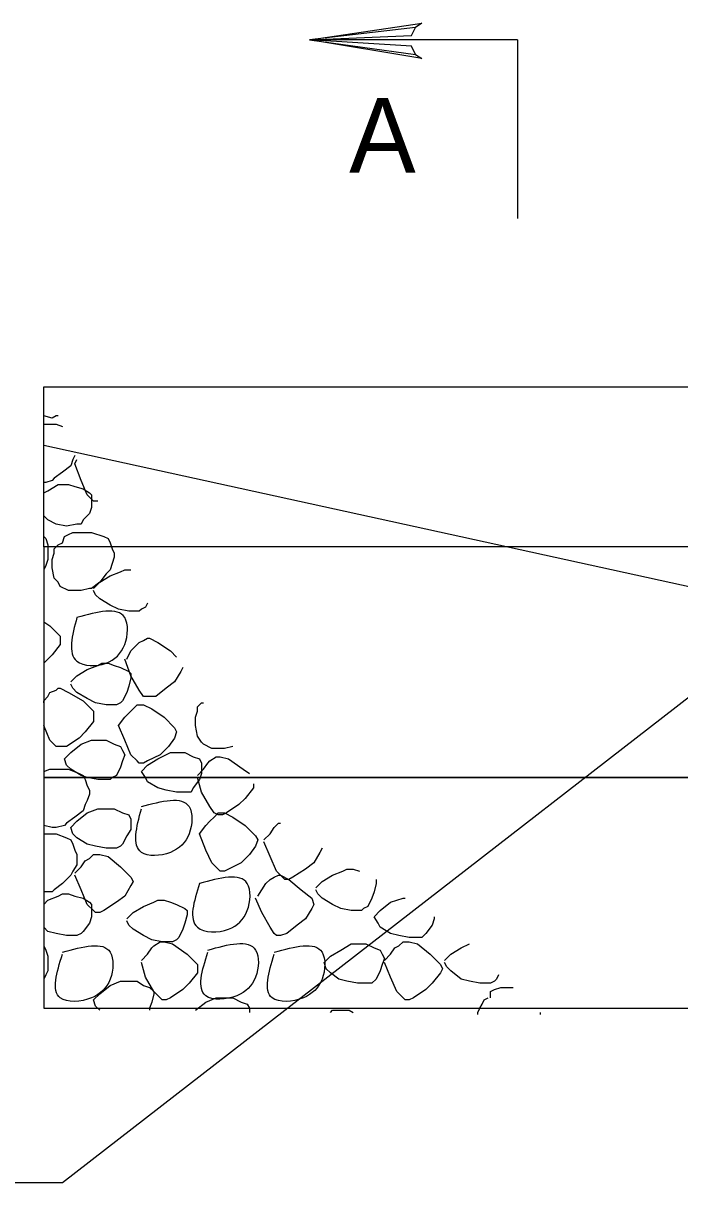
# Model space of a CAD drawing. Extents: x 593 to 1473, y 721 to 1315.
# Drawn here: x 708.2 to 747.7, y 825.5 to 895.3 of the extents above; entities that cross this region are included whole.
import ezdxf

# ---------------------------------------------------------------- set-up
doc = ezdxf.new("R2010")
doc.units = 0
doc.layers.add('2', color=7, linetype='Continuous')

msp = doc.modelspace()

# ---------------------------------------------------------------- linework, layer by layer
at = {"layer": '2'}
for p, q in [((737.959, 894.266), (725.459, 894.266)), ((737.959, 894.266), (737.959, 883.516)), ((709.459, 869.891), (769.334, 856.766)), ((754.959, 859.891), (710.584, 825.516)), ((710.584, 825.516), (663.834, 825.516))]:
    msp.add_line(p, q, dxfattribs=at)
for points in [[(731.834, 893.391), (731.584, 893.891), (725.459, 894.266), (731.834, 893.391), (732.209, 893.141), (725.459, 894.266), (731.584, 894.516), (731.834, 895.016), (725.459, 894.266), (732.209, 895.266), (731.834, 895.016)], [(709.459, 863.766), (709.459, 873.391), (765.709, 873.391)], [(709.959, 871.516), (709.459, 871.641)], [(709.459, 871.641), (709.459, 871.641)], [(710.209, 871.641), (709.959, 871.516)], [(710.334, 871.641), (710.209, 871.641)], [(709.459, 871.141), (709.709, 871.141)], [(709.709, 871.141), (710.209, 871.141)], [(710.209, 871.141), (710.584, 871.016)], [(711.334, 869.266), (711.209, 869.016)], [(711.084, 868.641), (710.584, 868.266)], [(711.209, 869.016), (711.084, 868.641)], [(711.334, 868.766), (711.459, 869.016)], [(711.709, 867.766), (711.334, 868.766)], [(709.959, 867.766), (709.584, 867.641)], [(710.084, 867.891), (709.959, 867.766)], [(710.584, 868.266), (710.084, 867.891)], [(712.084, 866.891), (711.709, 867.766)], [(709.584, 867.641), (709.459, 867.641)], [(709.459, 867.016), (709.709, 867.141)], [(709.709, 867.141), (710.334, 867.516)], [(710.334, 867.516), (710.584, 867.516)], [(710.584, 867.516), (710.959, 867.516)], [(710.959, 867.516), (711.334, 867.391)], [(711.334, 867.391), (711.834, 867.266)], [(711.834, 867.266), (712.209, 867.016)], [(712.209, 867.016), (712.334, 866.891)], [(712.459, 866.516), (712.084, 866.891)], [(712.334, 866.891), (712.334, 866.641)], [(712.334, 866.641), (712.334, 866.141)], [(712.584, 866.516), (712.459, 866.516)], [(712.709, 866.516), (712.584, 866.516)], [(709.709, 865.391), (709.459, 865.641)], [(712.209, 865.766), (711.834, 865.391)], [(712.334, 866.141), (712.209, 865.766)], [(710.209, 865.141), (709.709, 865.391)], [(710.834, 865.016), (710.209, 865.141)], [(711.459, 865.141), (710.834, 865.016)], [(711.709, 865.141), (711.459, 865.141)], [(711.834, 865.391), (711.709, 865.141)], [(709.459, 864.391), (709.584, 864.266)], [(709.584, 864.266), (709.709, 863.891)], [(710.584, 864.016), (710.709, 864.391)], [(710.709, 864.391), (710.959, 864.516)], [(710.959, 864.516), (711.209, 864.641)], [(711.209, 864.641), (711.834, 864.641)], [(711.834, 864.641), (712.334, 864.641)], [(712.334, 864.641), (713.084, 864.391)], [(713.084, 864.391), (713.334, 864.266)], [(713.334, 864.266), (713.459, 864.016)], [(769.459, 863.766), (709.459, 863.766), (709.459, 849.891), (786.959, 849.891), (786.959, 857.141)], [(770.334, 863.766), (709.459, 863.766)], [(709.709, 863.891), (709.709, 863.516)], [(709.709, 863.516), (709.709, 863.266)], [(710.084, 863.641), (710.334, 863.891)], [(710.084, 863.391), (710.084, 863.641)], [(710.334, 863.891), (710.584, 864.016)], [(713.459, 864.016), (713.584, 863.641)], [(713.584, 863.641), (713.709, 863.391)], [(709.709, 863.016), (709.584, 862.641)], [(709.709, 863.266), (709.709, 863.016)], [(709.959, 863.016), (710.084, 863.391)], [(709.959, 862.516), (709.959, 863.016)], [(713.709, 863.141), (713.584, 862.766)], [(713.709, 863.391), (713.709, 863.141)], [(709.584, 862.641), (709.459, 862.391)], [(710.084, 861.891), (709.959, 862.516)], [(713.209, 862.141), (712.834, 861.641)], [(713.459, 862.391), (713.209, 862.141)], [(713.584, 862.766), (713.459, 862.391)], [(713.459, 862.016), (714.084, 862.266)], [(714.084, 862.266), (714.334, 862.391)], [(714.334, 862.391), (714.709, 862.391)], [(714.709, 862.391), (714.709, 862.391)], [(710.334, 861.641), (710.084, 861.891)], [(710.459, 861.391), (710.334, 861.641)], [(712.834, 861.641), (712.334, 861.266)], [(712.459, 861.266), (712.834, 861.641)], [(712.834, 861.641), (713.459, 862.016)], [(710.959, 861.141), (710.459, 861.391)], [(711.459, 861.141), (710.959, 861.141)], [(711.709, 861.141), (711.459, 861.141)], [(712.209, 861.266), (711.709, 861.141)], [(712.334, 861.266), (712.209, 861.266)], [(712.584, 860.891), (712.459, 861.141)], [(712.834, 860.641), (712.584, 860.891)], [(713.459, 860.266), (712.834, 860.641)], [(713.959, 860.016), (713.459, 860.266)], [(715.584, 860.141), (715.334, 860.016)], [(715.709, 860.391), (715.584, 860.141)], [(714.584, 859.891), (713.959, 860.016)], [(715.209, 859.891), (714.584, 859.891)], [(715.334, 860.016), (715.209, 859.891)], [(709.459, 859.266), (709.834, 859.016)], [(709.834, 859.016), (710.459, 858.391)], [(710.459, 858.391), (710.459, 858.141)], [(710.459, 858.141), (710.459, 857.891)], [(714.959, 857.766), (715.209, 858.016)], [(715.209, 858.016), (715.459, 858.141)], [(715.459, 858.141), (715.709, 858.266)], [(715.709, 858.266), (715.834, 858.266)], [(715.834, 858.266), (716.334, 858.016)], [(716.334, 858.016), (717.084, 857.516)], [(709.959, 857.266), (709.584, 856.891)], [(710.459, 857.891), (709.959, 857.266)], [(714.459, 857.016), (714.709, 857.516)], [(714.709, 857.516), (714.959, 857.766)], [(717.084, 857.516), (717.459, 857.141)], [(709.584, 856.891), (709.459, 856.766)], [(712.084, 856.391), (712.709, 856.641)], [(712.709, 856.641), (712.959, 856.766)], [(712.959, 856.766), (713.334, 856.766)], [(713.334, 856.766), (713.709, 856.641)], [(713.709, 856.641), (714.084, 856.516)], [(714.709, 856.016), (714.334, 857.016)], [(711.084, 855.641), (711.459, 856.016)], [(711.459, 856.016), (712.084, 856.391)], [(714.084, 856.516), (714.584, 856.266)], [(714.584, 856.266), (714.709, 856.141)], [(714.709, 855.891), (714.584, 855.391)], [(714.709, 856.141), (714.709, 855.891)], [(715.209, 855.141), (714.709, 856.016)], [(717.709, 856.266), (717.334, 855.641)], [(717.834, 856.516), (717.709, 856.266)], [(709.834, 855.016), (710.209, 855.141)], [(710.209, 855.141), (710.334, 855.266)], [(710.334, 855.266), (710.459, 855.266)], [(710.459, 855.266), (710.959, 855.016)], [(711.209, 855.266), (711.084, 855.516)], [(711.459, 855.016), (711.209, 855.266)], [(714.584, 855.391), (714.459, 855.016)], [(715.459, 854.766), (715.209, 855.141)], [(716.834, 855.266), (716.209, 854.766)], [(717.334, 855.641), (716.834, 855.266)], [(709.459, 854.516), (709.709, 854.766)], [(709.459, 854.391), (709.459, 854.516)], [(709.709, 854.766), (709.834, 855.016)], [(710.959, 855.016), (711.834, 854.516)], [(712.084, 854.641), (711.459, 855.016)], [(711.834, 854.516), (712.459, 853.891)], [(712.584, 854.391), (712.084, 854.641)], [(714.209, 854.516), (714.084, 854.391)], [(714.459, 855.016), (714.209, 854.516)], [(715.709, 854.766), (715.459, 854.766)], [(715.834, 854.766), (715.709, 854.766)], [(716.209, 854.766), (715.834, 854.766)], [(712.459, 853.891), (712.459, 853.516)], [(713.209, 854.266), (712.584, 854.391)], [(713.834, 854.266), (713.209, 854.266)], [(714.084, 854.391), (713.834, 854.266)], [(714.334, 853.516), (714.584, 853.766)], [(714.584, 853.766), (714.834, 854.016)], [(714.834, 854.016), (715.084, 854.266)], [(715.084, 854.266), (715.209, 854.266)], [(715.209, 854.266), (715.459, 854.266)], [(715.459, 854.266), (715.959, 854.016)], [(715.959, 854.016), (716.709, 853.516)], [(718.584, 853.516), (718.709, 853.891)], [(718.709, 854.141), (718.959, 854.391)], [(718.709, 853.891), (718.709, 854.141)], [(718.959, 854.391), (719.084, 854.391)], [(712.459, 853.266), (711.959, 852.641)], [(712.459, 853.516), (712.459, 853.266)], [(713.959, 853.016), (714.334, 853.516)], [(716.709, 853.516), (717.334, 852.891)], [(718.584, 853.016), (718.584, 853.516)], [(709.834, 852.141), (709.459, 853.016)], [(711.959, 852.641), (711.584, 852.266)], [(714.334, 852.141), (713.959, 853.016)], [(717.334, 852.891), (717.459, 852.641)], [(717.459, 852.641), (717.334, 852.266)], [(718.709, 852.391), (718.584, 853.016)], [(718.959, 852.016), (718.709, 852.391)], [(710.209, 851.766), (709.834, 852.141)], [(710.334, 851.766), (710.209, 851.766)], [(710.584, 851.766), (710.334, 851.766)], [(710.834, 851.766), (710.584, 851.766)], [(711.584, 852.266), (710.834, 851.766)], [(711.084, 851.391), (711.709, 851.891)], [(711.709, 851.891), (712.334, 852.141)], [(712.334, 852.141), (712.584, 852.141)], [(712.584, 852.141), (712.959, 852.141)], [(712.959, 852.141), (713.209, 852.141)], [(713.209, 852.141), (713.709, 851.891)], [(713.709, 851.891), (714.084, 851.766)], [(714.084, 851.766), (714.209, 851.516)], [(714.709, 851.266), (714.334, 852.141)], [(716.959, 851.766), (716.459, 851.266)], [(717.334, 852.266), (716.959, 851.766)], [(719.084, 851.891), (718.959, 852.016)], [(719.584, 851.641), (719.084, 851.891)], [(720.834, 851.766), (720.334, 851.641)], [(710.709, 851.016), (711.084, 851.391)], [(710.834, 850.641), (710.709, 851.016)], [(714.209, 851.516), (714.334, 851.266)], [(714.334, 851.266), (714.209, 850.891)], [(715.084, 850.891), (714.709, 851.266)], [(716.459, 851.266), (715.709, 850.891)], [(715.709, 850.641), (716.334, 851.016)], [(716.334, 851.016), (717.084, 851.391)], [(717.084, 851.391), (717.209, 851.391)], [(717.209, 851.391), (717.709, 851.391)], [(717.709, 851.391), (717.959, 851.391)], [(717.959, 851.391), (718.459, 851.141)], [(718.459, 851.141), (718.834, 851.016)], [(718.834, 851.016), (718.959, 850.766)], [(719.459, 850.891), (719.834, 851.141)], [(720.084, 851.641), (719.584, 851.641)], [(719.834, 851.141), (719.959, 851.141)], [(719.959, 851.141), (720.084, 851.141)], [(720.334, 851.641), (720.084, 851.641)], [(720.084, 851.141), (720.584, 851.016)], [(720.584, 851.016), (721.459, 850.391)], [(709.459, 850.266), (709.834, 850.391)], [(709.459, 850.266), (709.459, 850.266)], [(709.834, 850.391), (710.459, 850.391)], [(710.459, 850.391), (710.959, 850.391)], [(711.084, 850.391), (710.834, 850.641)], [(710.959, 850.391), (711.584, 850.141)], [(711.709, 850.016), (711.084, 850.391)], [(714.084, 850.516), (713.834, 850.016)], [(714.209, 850.891), (714.084, 850.516)], [(715.209, 850.766), (715.084, 850.891)], [(715.459, 850.766), (715.209, 850.766)], [(715.334, 850.266), (715.709, 850.641)], [(715.584, 849.891), (715.334, 850.266)], [(715.709, 850.891), (715.459, 850.766)], [(718.709, 850.016), (719.084, 850.391)], [(718.959, 850.766), (718.959, 850.516)], [(718.959, 850.516), (718.959, 850.141)], [(719.084, 850.391), (719.334, 850.766)], [(719.334, 850.766), (719.459, 850.891)], [(721.459, 850.391), (721.834, 850.141)], [(711.584, 850.141), (711.834, 850.016)], [(712.084, 849.891), (711.709, 850.016)], [(711.834, 850.016), (711.959, 849.766)], [(711.959, 849.766), (712.084, 849.391)], [(712.709, 849.766), (712.084, 849.891)], [(713.459, 849.766), (712.709, 849.766)], [(713.584, 849.891), (713.459, 849.766)], [(713.834, 850.016), (713.584, 849.891)], [(715.709, 849.641), (715.584, 849.891)], [(716.334, 849.266), (715.709, 849.641)], [(718.834, 849.766), (718.459, 849.266)], [(718.959, 849.016), (718.709, 849.891)], [(718.959, 850.141), (718.834, 849.766)], [(712.084, 849.391), (712.209, 849.141)], [(712.209, 848.891), (712.084, 848.516)], [(712.209, 849.141), (712.209, 848.891)], [(716.834, 849.141), (716.334, 849.266)], [(717.459, 849.016), (716.834, 849.141)], [(718.209, 849.016), (717.459, 849.016)], [(718.334, 849.016), (718.209, 849.016)], [(718.459, 849.266), (718.334, 849.016)], [(719.459, 848.141), (718.959, 849.016)], [(722.084, 849.266), (721.584, 848.641)], [(722.084, 849.516), (722.084, 849.266)], [(711.959, 848.266), (711.834, 847.891)], [(712.084, 848.516), (711.959, 848.266)], [(721.209, 848.266), (720.459, 847.766)], [(721.584, 848.641), (721.209, 848.266)], [(711.334, 847.516), (710.834, 847.141)], [(711.834, 847.891), (711.334, 847.516)], [(711.459, 847.266), (712.084, 847.766)], [(712.084, 847.766), (712.709, 848.016)], [(712.709, 848.016), (712.959, 848.016)], [(712.959, 848.016), (713.334, 848.016)], [(713.334, 848.016), (713.709, 848.016)], [(713.709, 848.016), (714.209, 847.766)], [(714.209, 847.766), (714.584, 847.641)], [(714.584, 847.641), (714.709, 847.391)], [(719.709, 847.766), (719.459, 848.141)], [(719.459, 847.266), (719.709, 847.516)], [(719.709, 847.516), (719.959, 847.766)], [(719.959, 847.641), (719.709, 847.766)], [(719.959, 847.766), (720.084, 847.766)], [(720.209, 847.641), (719.959, 847.641)], [(720.084, 847.766), (720.334, 847.766)], [(720.459, 847.766), (720.209, 847.641)], [(720.334, 847.766), (720.834, 847.516)], [(720.834, 847.516), (721.584, 847.016)], [(709.959, 846.891), (709.459, 847.016)], [(709.459, 847.016), (709.459, 847.016)], [(710.209, 846.891), (709.959, 846.891)], [(710.709, 847.016), (710.209, 846.891)], [(710.834, 847.141), (710.709, 847.016)], [(711.084, 846.891), (711.459, 847.266)], [(711.209, 846.516), (711.084, 846.891)], [(714.709, 846.766), (714.459, 846.391)], [(714.709, 847.391), (714.709, 847.266)], [(714.709, 847.266), (714.709, 846.766)], [(718.834, 846.516), (719.209, 847.016)], [(719.209, 847.016), (719.459, 847.266)], [(721.584, 847.016), (722.209, 846.391)], [(723.084, 846.516), (723.334, 846.891)], [(723.334, 846.891), (723.584, 847.141)], [(723.584, 847.141), (723.709, 847.141)], [(709.459, 846.516), (709.709, 846.516)], [(709.709, 846.516), (710.209, 846.516)], [(710.209, 846.516), (710.834, 846.266)], [(710.834, 846.266), (711.084, 846.141)], [(711.084, 846.141), (711.209, 845.891)], [(711.459, 846.266), (711.209, 846.516)], [(712.084, 845.891), (711.459, 846.266)], [(714.459, 846.391), (714.209, 845.891)], [(719.209, 845.516), (718.834, 846.516)], [(722.209, 846.391), (722.334, 846.141)], [(722.334, 846.141), (722.209, 845.766)], [(722.709, 846.141), (723.084, 846.516)], [(711.209, 845.891), (711.334, 845.516)], [(711.334, 845.516), (711.459, 845.266)], [(712.584, 845.766), (712.084, 845.891)], [(713.209, 845.641), (712.584, 845.766)], [(713.834, 845.641), (713.209, 845.641)], [(714.084, 845.766), (713.834, 845.641)], [(714.209, 845.891), (714.084, 845.766)], [(719.584, 844.766), (719.209, 845.516)], [(722.209, 845.766), (721.834, 845.266)], [(723.084, 845.141), (722.709, 846.016)], [(726.084, 845.391), (725.709, 844.766)], [(726.209, 845.641), (726.084, 845.391)], [(726.209, 845.641), (726.209, 845.641)], [(711.459, 845.266), (711.459, 845.016)], [(711.459, 845.016), (711.459, 844.641)], [(711.709, 844.516), (711.959, 844.891)], [(711.959, 844.891), (712.209, 845.016)], [(712.209, 845.016), (712.459, 845.266)], [(712.459, 845.266), (712.584, 845.266)], [(712.584, 845.266), (712.834, 845.266)], [(712.834, 845.266), (713.334, 845.141)], [(713.334, 845.141), (714.084, 844.516)], [(719.959, 844.391), (719.584, 844.766)], [(721.334, 844.766), (720.584, 844.391)], [(721.834, 845.266), (721.334, 844.766)], [(723.459, 844.266), (723.084, 845.141)], [(725.709, 844.766), (725.209, 844.391)], [(711.084, 844.016), (710.584, 843.516)], [(711.209, 844.266), (711.084, 844.016)], [(711.459, 844.641), (711.209, 844.266)], [(711.334, 844.141), (711.709, 844.516)], [(711.709, 843.141), (711.334, 844.016)], [(714.084, 844.516), (714.709, 843.891)], [(720.084, 844.266), (719.959, 844.391)], [(720.334, 844.266), (720.084, 844.266)], [(720.584, 844.391), (720.334, 844.266)], [(723.334, 843.891), (723.584, 844.016)], [(723.834, 843.891), (723.459, 844.266)], [(723.584, 844.016), (723.709, 844.016)], [(723.709, 844.016), (724.209, 843.766)], [(725.209, 844.391), (724.459, 843.891)], [(726.209, 843.641), (726.834, 844.016)], [(726.834, 844.016), (727.459, 844.266)], [(727.459, 844.266), (727.709, 844.391)], [(727.709, 844.391), (728.084, 844.391)], [(728.084, 844.391), (728.459, 844.266)], [(728.459, 844.266), (728.459, 844.266)], [(710.584, 843.516), (710.084, 843.141)], [(714.709, 843.391), (714.334, 842.766)], [(714.709, 843.891), (714.834, 843.641)], [(714.834, 843.641), (714.709, 843.391)], [(722.584, 843.141), (722.834, 843.516)], [(722.834, 843.516), (723.084, 843.766)], [(723.084, 843.766), (723.334, 843.891)], [(723.959, 843.766), (723.834, 843.891)], [(724.209, 843.766), (723.959, 843.766)], [(724.459, 843.891), (724.209, 843.766)], [(724.209, 843.766), (724.959, 843.141)], [(725.834, 843.266), (726.209, 843.641)], [(729.459, 843.516), (729.334, 843.016)], [(729.459, 843.766), (729.459, 843.516)], [(709.584, 843.016), (709.459, 843.016)], [(709.959, 843.016), (709.584, 843.016)], [(709.709, 842.516), (710.334, 842.766)], [(710.084, 843.141), (709.959, 843.016)], [(710.334, 842.766), (710.584, 842.891)], [(710.584, 842.891), (710.959, 842.891)], [(710.959, 842.891), (711.334, 842.766)], [(711.334, 842.766), (711.834, 842.641)], [(712.084, 842.266), (711.709, 843.141)], [(711.834, 842.641), (712.209, 842.391)], [(714.334, 842.766), (713.834, 842.391)], [(722.584, 841.766), (722.209, 842.641)], [(722.334, 842.766), (722.584, 843.141)], [(724.959, 843.141), (725.584, 842.641)], [(725.584, 842.641), (725.709, 842.266)], [(725.959, 842.891), (725.834, 843.141)], [(726.209, 842.641), (725.959, 842.891)], [(726.834, 842.266), (726.209, 842.641)], [(729.209, 842.641), (728.959, 842.141)], [(729.334, 843.016), (729.209, 842.641)], [(730.334, 842.391), (731.084, 842.641)], [(731.084, 842.641), (731.209, 842.641)], [(709.459, 842.266), (709.709, 842.516)], [(712.459, 841.891), (712.084, 842.266)], [(712.209, 842.391), (712.334, 842.266)], [(712.334, 842.266), (712.334, 842.016)], [(712.334, 842.016), (712.334, 841.516)], [(712.584, 841.766), (712.459, 841.891)], [(713.084, 841.891), (712.834, 841.766)], [(713.834, 842.391), (713.084, 841.891)], [(714.834, 841.766), (715.459, 842.141)], [(715.459, 842.141), (716.084, 842.391)], [(716.084, 842.391), (716.334, 842.516)], [(716.334, 842.516), (716.709, 842.516)], [(716.709, 842.516), (717.084, 842.391)], [(717.084, 842.391), (717.459, 842.266)], [(717.459, 842.266), (717.959, 842.016)], [(717.959, 842.016), (718.084, 841.891)], [(718.084, 841.891), (718.084, 841.641)], [(725.584, 842.016), (725.209, 841.391)], [(725.709, 842.266), (725.584, 842.016)], [(727.334, 842.016), (726.834, 842.266)], [(727.959, 841.891), (727.334, 842.016)], [(728.584, 841.891), (727.959, 841.891)], [(728.709, 842.016), (728.584, 841.891)], [(728.959, 842.141), (728.709, 842.016)], [(729.334, 841.516), (729.709, 841.891)], [(729.709, 841.891), (730.334, 842.391)], [(712.334, 841.516), (712.209, 841.141)], [(712.834, 841.766), (712.584, 841.766)], [(714.459, 841.391), (714.834, 841.766)], [(714.584, 841.016), (714.459, 841.266)], [(718.084, 841.641), (717.959, 841.141)], [(723.084, 840.891), (722.584, 841.766)], [(725.209, 841.391), (724.709, 841.016)], [(729.584, 841.141), (729.334, 841.516)], [(732.959, 841.391), (732.834, 841.016)], [(732.959, 841.516), (732.959, 841.391)], [(709.709, 840.641), (709.459, 840.891)], [(710.209, 840.516), (709.709, 840.641)], [(710.834, 840.391), (710.209, 840.516)], [(711.709, 840.516), (711.459, 840.391)], [(711.834, 840.641), (711.709, 840.516)], [(712.209, 841.141), (711.834, 840.641)], [(714.834, 840.766), (714.584, 841.016)], [(715.459, 840.391), (714.834, 840.766)], [(717.834, 840.766), (717.584, 840.266)], [(717.959, 841.141), (717.834, 840.766)], [(723.334, 840.516), (723.084, 840.891)], [(723.459, 840.391), (723.334, 840.516)], [(724.084, 840.516), (723.709, 840.391)], [(724.709, 841.016), (724.084, 840.516)], [(729.709, 840.891), (729.584, 841.141)], [(730.334, 840.516), (729.709, 840.891)], [(730.834, 840.391), (730.334, 840.516)], [(732.459, 840.516), (732.334, 840.391)], [(732.834, 841.016), (732.459, 840.516)], [(711.459, 840.391), (710.834, 840.391)], [(715.959, 840.141), (715.459, 840.391)], [(716.584, 840.016), (715.959, 840.141)], [(716.084, 839.766), (716.459, 840.016)], [(716.459, 840.016), (716.584, 840.016)], [(716.584, 840.016), (716.709, 840.016)], [(717.209, 840.016), (716.584, 840.016)], [(716.709, 840.016), (717.209, 839.891)], [(717.459, 840.141), (717.209, 840.016)], [(717.209, 839.891), (718.084, 839.266)], [(717.584, 840.266), (717.459, 840.141)], [(723.709, 840.391), (723.459, 840.391)], [(727.334, 839.516), (727.959, 839.891)], [(727.959, 839.891), (728.084, 839.891)], [(728.084, 839.891), (728.584, 839.891)], [(728.584, 839.891), (728.834, 839.891)], [(728.834, 839.891), (729.334, 839.641)], [(731.459, 840.266), (730.834, 840.391)], [(730.834, 839.766), (731.084, 840.016)], [(731.084, 840.016), (731.209, 840.016)], [(731.209, 840.016), (731.459, 840.016)], [(732.209, 840.266), (731.459, 840.266)], [(731.459, 840.016), (731.959, 839.891)], [(731.959, 839.891), (732.709, 839.266)], [(732.334, 840.391), (732.209, 840.266)], [(734.584, 839.641), (735.084, 839.891)], [(709.459, 839.766), (709.584, 839.516)], [(709.584, 839.516), (709.709, 839.141)], [(709.709, 839.141), (709.709, 838.891)], [(715.334, 838.891), (715.709, 839.266)], [(715.709, 839.266), (715.959, 839.641)], [(715.959, 839.641), (716.084, 839.766)], [(718.084, 839.266), (718.709, 838.641)], [(726.334, 838.766), (726.709, 839.141)], [(726.709, 839.141), (727.334, 839.516)], [(729.334, 839.641), (729.709, 839.516)], [(729.709, 839.516), (729.834, 839.266)], [(729.834, 839.266), (729.959, 839.016)], [(729.959, 838.891), (730.334, 839.266)], [(730.334, 839.266), (730.584, 839.641)], [(730.584, 839.641), (730.834, 839.766)], [(732.709, 839.266), (733.334, 838.641)], [(733.584, 838.891), (733.959, 839.266)], [(733.959, 839.266), (734.584, 839.641)], [(709.709, 838.891), (709.709, 838.641)], [(709.709, 838.641), (709.709, 838.266)], [(715.584, 837.891), (715.334, 838.766)], [(718.709, 838.641), (718.709, 838.391)], [(726.459, 838.391), (726.334, 838.766)], [(729.834, 838.641), (729.709, 838.266)], [(729.959, 839.016), (729.834, 838.641)], [(730.334, 837.891), (729.959, 838.766)], [(733.334, 838.641), (733.459, 838.391)], [(733.709, 838.516), (733.584, 838.766)], [(733.959, 838.266), (733.709, 838.516)], [(709.584, 838.016), (709.459, 837.766)], [(709.709, 838.266), (709.584, 838.016)], [(716.084, 837.016), (715.584, 837.891)], [(718.709, 838.141), (718.209, 837.516)], [(718.709, 838.391), (718.709, 838.141)], [(726.709, 838.141), (726.459, 838.391)], [(727.209, 837.766), (726.709, 838.141)], [(727.709, 837.641), (727.209, 837.766)], [(729.459, 837.766), (729.209, 837.516)], [(729.709, 838.266), (729.459, 837.766)], [(730.709, 837.016), (730.334, 837.891)], [(733.334, 838.141), (732.834, 837.516)], [(733.459, 838.391), (733.334, 838.141)], [(734.584, 837.766), (733.959, 838.266)], [(735.084, 837.641), (734.584, 837.766)], [(736.709, 837.766), (736.584, 837.641)], [(736.834, 838.016), (736.709, 837.766)], [(712.834, 836.891), (713.459, 837.391)], [(713.459, 837.391), (714.084, 837.641)], [(714.084, 837.641), (714.334, 837.641)], [(714.334, 837.641), (714.709, 837.641)], [(714.709, 837.641), (715.084, 837.641)], [(715.084, 837.641), (715.459, 837.391)], [(715.459, 837.391), (715.834, 837.266)], [(715.834, 837.266), (716.084, 837.016)], [(716.459, 836.641), (716.084, 837.016)], [(716.084, 837.016), (716.084, 836.891)], [(717.834, 837.141), (717.084, 836.641)], [(718.209, 837.516), (717.834, 837.141)], [(728.334, 837.516), (727.709, 837.641)], [(729.084, 837.516), (728.334, 837.516)], [(729.209, 837.516), (729.084, 837.516)], [(731.084, 836.641), (730.709, 837.016)], [(732.459, 837.141), (731.709, 836.641)], [(732.834, 837.516), (732.459, 837.141)], [(735.709, 837.516), (735.084, 837.641)], [(736.334, 837.516), (735.709, 837.516)], [(736.584, 837.641), (736.334, 837.516)], [(736.334, 837.016), (736.584, 837.141)], [(736.334, 836.641), (736.334, 837.016)], [(736.584, 837.141), (736.959, 837.266)], [(736.959, 837.266), (737.584, 837.266)], [(737.584, 837.266), (737.709, 837.266)], [(712.459, 836.516), (712.834, 836.891)], [(712.584, 836.141), (712.459, 836.516)], [(715.959, 836.391), (715.834, 836.016)], [(716.084, 836.891), (715.959, 836.391)], [(716.584, 836.516), (716.459, 836.641)], [(716.834, 836.516), (716.584, 836.516)], [(717.084, 836.641), (716.834, 836.516)], [(718.584, 835.891), (719.209, 836.391)], [(719.209, 836.391), (719.834, 836.641)], [(719.834, 836.641), (720.084, 836.641)], [(720.084, 836.641), (720.459, 836.641)], [(720.459, 836.641), (720.834, 836.641)], [(720.834, 836.641), (721.334, 836.391)], [(721.334, 836.391), (721.709, 836.266)], [(731.209, 836.516), (731.084, 836.641)], [(731.459, 836.516), (731.209, 836.516)], [(731.709, 836.641), (731.459, 836.516)], [(735.834, 836.266), (735.959, 836.516)], [(735.959, 836.516), (736.209, 836.641)], [(712.834, 835.891), (712.584, 836.141)], [(712.834, 835.891), (712.834, 835.891)], [(715.834, 836.016), (715.834, 835.891)], [(718.584, 835.891), (718.584, 835.891)], [(721.709, 836.266), (721.834, 836.016)], [(721.834, 836.016), (721.834, 835.766)], [(721.834, 835.766), (721.834, 835.766)], [(726.709, 835.766), (726.834, 835.891)], [(726.834, 835.891), (727.084, 835.891)], [(727.084, 835.891), (727.459, 835.891)], [(727.459, 835.891), (727.834, 835.891)], [(727.834, 835.891), (728.084, 835.766)], [(735.584, 835.766), (735.709, 836.016)], [(735.584, 835.641), (735.584, 835.766)], [(735.709, 836.016), (735.834, 836.266)], [(739.334, 835.766), (739.334, 835.641)]]:
    msp.add_lwpolyline(points, dxfattribs=at)
msp.add_lwpolyline([(709.459, 849.891), (709.459, 836.016), (786.959, 836.016), (786.959, 849.891)], close=True, dxfattribs=at)
for points in [[(711.459, 859.516), (714.334, 859.516), (714.334, 857.891), (713.209, 856.766), (711.459, 856.891), (711.459, 859.516)], [(715.334, 848.141), (718.209, 848.141), (718.209, 846.516), (717.084, 845.391), (715.334, 845.391), (715.334, 848.016)], [(718.834, 843.516), (721.709, 843.516), (721.709, 841.891), (720.584, 840.766), (718.709, 840.891), (718.834, 843.516)], [(710.584, 839.391), (713.459, 839.391), (713.459, 837.766), (712.334, 836.641), (710.459, 836.641), (710.584, 839.266)], [(719.334, 839.516), (722.209, 839.516), (722.209, 837.891), (721.084, 836.766), (719.209, 836.766), (719.334, 839.391)], [(723.334, 839.391), (726.209, 839.391), (726.209, 837.766), (725.084, 836.641), (723.209, 836.641), (723.334, 839.266)]]:
    msp.add_spline(points, degree=3, dxfattribs=at)

# ---------------------------------------------------------------- texts
msp.add_text('A', height=4.5, dxfattribs=at).set_placement((727.834, 886.266))

doc.saveas('drawing.dxf')
